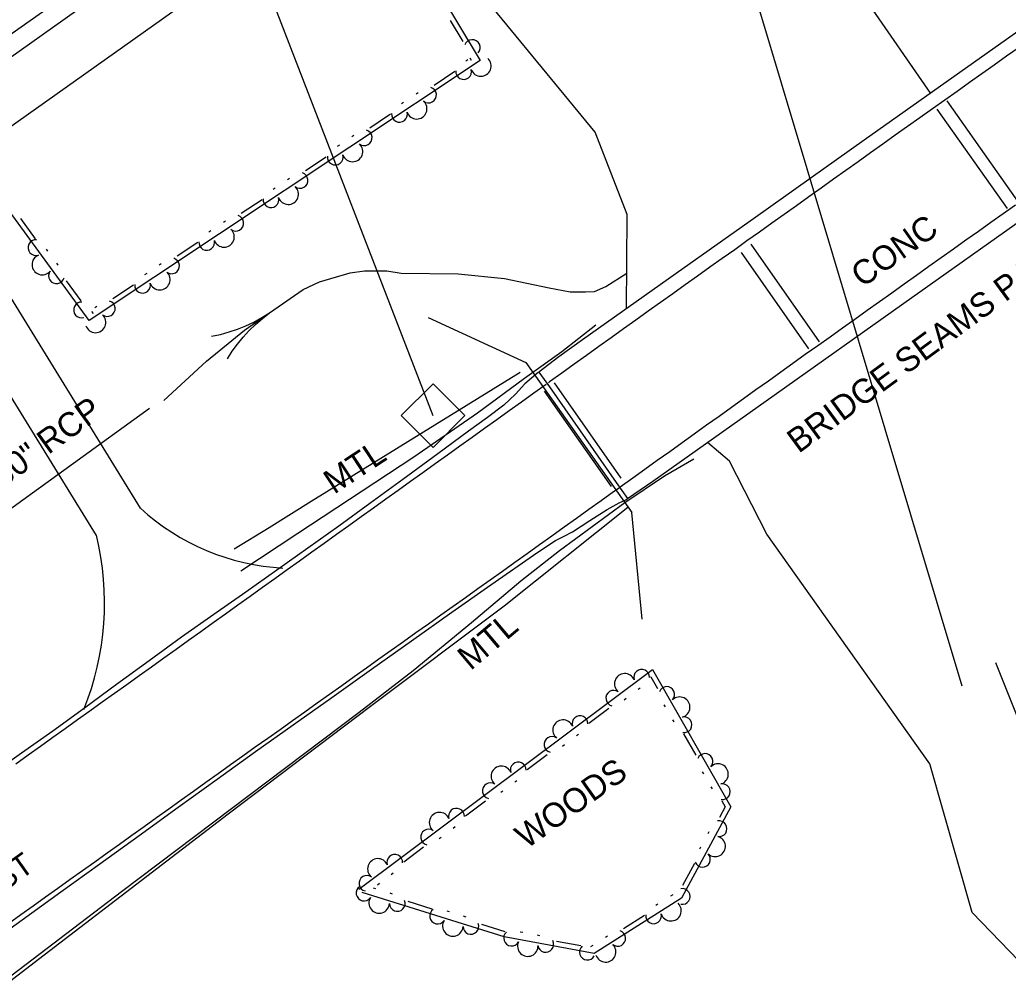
# Model space of a CAD drawing. Extents: x 1577032 to 1581865, y 611492 to 615011.
# Drawn here: x 1579630.9 to 1579793.8, y 613198.6 to 613356.4 of the extents above; entities that cross this region are included whole.
import ezdxf

# ---------------------------------------------------------------- set-up
doc = ezdxf.new("R2010")
doc.units = 0
for name, color, linetype in [('CTL Supplemental Horizontal and Vertical CELL', 7, 'Continuous'), ('Exist Guardrail', 7, 'Continuous'), ('Exist Guardrail Text', 7, 'Continuous'), ('Exist Horizontal Baseline Alignment Station Label', 7, 'Continuous'), ('Exist Hydro Jurisdictional Stream or Body of Water', 7, 'Continuous'), ('Exist Hydro Stream Flow Arrow CELL', 7, 'Continuous'), ('Exist Hydro Stream or Body of Water', 7, 'Continuous'), ('Exist Property Tie Line', 7, 'Continuous'), ('Exist Right of Way Line', 7, 'Continuous'), ('Exist Roads EOP', 7, 'Continuous'), ('Exist Roads EOP Text', 7, 'Continuous'), ('Exist Roads EOT', 7, 'Continuous'), ('Exist Structure Major Bridge Seam', 7, 'Continuous'), ('Exist Structure Major Bridge WW', 7, 'Continuous'), ('Exist Structure Major Deck Tunnel Box Culvert', 7, 'Continuous'), ('Exist Structure Major Deck Tunnel Box Culvert Text', 7, 'Continuous'), ('Exist Structure Minor Pipes RCP 30 Inch', 7, 'Continuous'), ('Exist Structure Minor Pipes RCP 30 Inch Text', 7, 'Continuous'), ('Exist Utilities Telephone UG FO SUE LOS B', 7, 'Continuous'), ('Exist Utilities Water UG Line SUE LOS B', 7, 'Continuous'), ('Exist Vegetation Woods Line Text', 7, 'Continuous'), ('Old_Level_11', 7, 'Continuous'), ('Old_Level_7', 7, 'Continuous'), ('Scratch_Level_3', 7, 'Continuous'), ('Scratch_Level_4', 7, 'Continuous')]:
    doc.layers.add(name, color=color, linetype=linetype)

msp = doc.modelspace()

# ---------------------------------------------------------------- linework, layer by layer
at = {"layer": 'CTL Supplemental Horizontal and Vertical CELL'}
msp.add_line((1579698.95, 613291.12), (1579698.95, 613291.12), dxfattribs=at)
msp.add_lwpolyline([(1579693.73, 613291.13), (1579698.97, 613296.38), (1579704.22, 613291.13), (1579698.98, 613285.88)], close=True, dxfattribs=at)
at = {"layer": 'Exist Guardrail'}
for points in [[(1579667.28, 613265.53), (1579676.67, 613271.75), (1579695.81, 613284.34), (1579706.32, 613291.56), (1579714.04, 613297.28), (1579720.19, 613301.68), (1579725.79, 613306.06)], [(1579741.96, 613283.96), (1579737.12, 613281.13), (1579730.57, 613276.73), (1579719.79, 613268.84), (1579713.42, 613263.83), (1579705.29, 613256.98), (1579695.7, 613249.06), (1579686.81, 613242.18), (1579647.6, 613212.65), (1579618.22, 613190.29), (1579587.73, 613167.25), (1579572.92, 613156.39), (1579515.84, 613115.84), (1579461.27, 613076.76), (1579417.23, 613045.78), (1579363.89, 613007.87), (1579309.01, 612968.33), (1579291.73, 612955.85)]]:
    msp.add_lwpolyline(points, dxfattribs=at)
at = {"layer": 'Exist Horizontal Baseline Alignment Station Label'}
msp.add_line((1579637.33, 613450.53), (1579698.95, 613291.12), dxfattribs=at)
at = {"layer": 'Exist Hydro Jurisdictional Stream or Body of Water'}
for points in [[(1579725.68, 613337.86), (1579702.45, 613366.13), (1579690.36, 613388.32), (1579685.84, 613407.56), (1579687.53, 613428.23), (1579681.01, 613453.54), (1579684.84, 613469.8), (1579686.57, 613483.26), (1579683.27, 613517.5), (1579681.81, 613542.23), (1579681.11, 613568.29), (1579677.24, 613598.35)], [(1579761.5, 613367.04), (1579770.44, 613359.38), (1579780.93, 613344.22)], [(1579730.85, 613308.77), (1579730.9, 613316.26), (1579730.95, 613324.27), (1579725.68, 613337.86)], [(1579831.32, 613164.67), (1579822.56, 613181.34), (1579806.35, 613190.1), (1579787.81, 613209.26), (1579780.85, 613233.72), (1579753.99, 613271.61), (1579747.82, 613283.64), (1579744.18, 613286.7)]]:
    msp.add_lwpolyline(points, dxfattribs=at)
at = {"layer": 'Exist Hydro Stream Flow Arrow CELL'}
msp.add_line((1579667.89, 613305.19), (1579667.89, 613305.19), dxfattribs=at)
for points in [[(1579662.47, 613304.23), (1579663.92, 613304.49), (1579665.35, 613304.93), (1579666.76, 613305.37), (1579668.1, 613305.92), (1579669.44, 613306.55), (1579670.75, 613307.27), (1579672, 613308.04)], [(1579665.08, 613300.46), (1579665.84, 613301.72), (1579666.75, 613302.91), (1579667.66, 613304.07), (1579668.64, 613305.14), (1579669.71, 613306.16), (1579670.84, 613307.14), (1579672, 613308.04)]]:
    msp.add_lwpolyline(points, dxfattribs=at)
at = {"layer": 'Exist Hydro Stream or Body of Water'}
msp.add_lwpolyline([(1579654.58, 613293.6), (1579661.66, 613300.1), (1579667.89, 613305.19), (1579677.59, 613311.91), (1579680.25, 613313.17), (1579685.29, 613314.64), (1579687.69, 613314.97), (1579691.37, 613314.97), (1579693.7, 613314.61), (1579703.1, 613314.47), (1579710.72, 613313.71), (1579718.12, 613312.17), (1579721.58, 613311.52), (1579724.08, 613311.5), (1579725.57, 613311.6), (1579727.45, 613312.38), (1579730.89, 613314.6)], dxfattribs=at)
at = {"layer": 'Exist Property Tie Line'}
for p, q in [((1579786.17, 613246.53), (1579735.91, 613414.45)), ((1579791.65, 613250.42), (1579814.68, 613192.73))]:
    msp.add_line(p, q, dxfattribs=at)
at = {"layer": 'Exist Right of Way Line'}
msp.add_line((1579178.76, 613018.8), (1580074.87, 613655.16), dxfattribs=at)
at = {"layer": 'Exist Roads EOP'}
for points in [[(1579716.3, 613298.21), (1579714.11, 613296.34), (1579712.54, 613294.68), (1579710.64, 613292.82), (1579707.97, 613290.83), (1579704.81, 613288.54), (1579699.78, 613284.85), (1579694, 613280.6), (1579688.56, 613276.63), (1579683.43, 613272.91), (1579678.34, 613269.27), (1579673.24, 613265.66), (1579668.1, 613262.05), (1579662.85, 613258.35), (1579657.51, 613254.59), (1579652.17, 613250.74), (1579646.82, 613246.8), (1579641.51, 613242.91), (1579636.3, 613239.15), (1579631.14, 613235.52), (1579625.91, 613231.84)], [(1579624.89, 613203.47), (1579631.25, 613208.06), (1579637.64, 613212.66), (1579644.08, 613217.29), (1579650.53, 613221.95), (1579656.98, 613226.61), (1579663.39, 613231.23), (1579669.7, 613235.75), (1579675.94, 613240.18), (1579682.3, 613244.69), (1579688.81, 613249.33), (1579695.42, 613254.02), (1579702.06, 613258.71), (1579708.5, 613263.24), (1579716.25, 613268.64), (1579719.16, 613270.54), (1579720.48, 613271.21), (1579721.94, 613271.97), (1579724.82, 613273.86), (1579727.66, 613275.63), (1579729.65, 613276.73), (1579730.73, 613277.27), (1579730.98, 613277.42)]]:
    msp.add_lwpolyline(points, dxfattribs=at)
at = {"layer": 'Exist Roads EOT'}
for points in [[(1579795.55, 613351.78), (1579793.5, 613350.33), (1579791.46, 613348.89), (1579789.42, 613347.44), (1579787.38, 613346), (1579785.34, 613344.55), (1579783.3, 613343.11), (1579781.26, 613341.66), (1579779.22, 613340.22), (1579777.18, 613338.77), (1579775.14, 613337.33), (1579773.11, 613335.88), (1579771.07, 613334.43), (1579769.04, 613332.97), (1579767, 613331.52), (1579764.96, 613330.07), (1579762.93, 613328.62), (1579760.89, 613327.17), (1579758.86, 613325.72), (1579756.82, 613324.27), (1579754.79, 613322.82), (1579752.75, 613321.37), (1579750.71, 613319.92), (1579748.68, 613318.47), (1579746.64, 613317.02), (1579744.61, 613315.56), (1579742.57, 613314.11), (1579740.53, 613312.66), (1579738.5, 613311.21), (1579736.46, 613309.76), (1579734.43, 613308.31), (1579732.39, 613306.86), (1579730.36, 613305.4), (1579728.33, 613303.95), (1579726.29, 613302.49), (1579724.26, 613301.03), (1579722.23, 613299.58), (1579720.2, 613298.12), (1579718.16, 613296.67), (1579717.99, 613296.54)], [(1579729.83, 613279.4), (1579731.87, 613280.86), (1579733.9, 613282.31), (1579735.93, 613283.77), (1579737.97, 613285.22), (1579740, 613286.68), (1579742.03, 613288.13), (1579744.06, 613289.59), (1579746.1, 613291.04), (1579748.13, 613292.5), (1579750.16, 613293.96), (1579752.19, 613295.41), (1579754.23, 613296.87), (1579756.26, 613298.32), (1579758.29, 613299.78), (1579760.32, 613301.23), (1579762.36, 613302.68), (1579764.4, 613304.13), (1579766.43, 613305.58), (1579768.47, 613307.03), (1579770.51, 613308.48), (1579772.54, 613309.93), (1579774.58, 613311.38), (1579776.62, 613312.83), (1579778.65, 613314.28), (1579780.69, 613315.73), (1579782.73, 613317.18), (1579784.76, 613318.63), (1579786.8, 613320.08), (1579788.84, 613321.53), (1579790.87, 613322.98), (1579792.91, 613324.43), (1579794.95, 613325.88)], [(1579717.6, 613296.27), (1579715.57, 613294.81), (1579713.54, 613293.35), (1579711.51, 613291.9), (1579709.48, 613290.44), (1579707.44, 613288.99), (1579705.41, 613287.53), (1579703.38, 613286.08), (1579701.35, 613284.62), (1579699.31, 613283.16), (1579697.28, 613281.71), (1579695.25, 613280.25), (1579693.22, 613278.8), (1579691.18, 613277.34), (1579689.15, 613275.89), (1579687.12, 613274.43), (1579685.09, 613272.98), (1579683.05, 613271.52), (1579681.02, 613270.07), (1579678.99, 613268.61), (1579676.95, 613267.16), (1579674.92, 613265.7), (1579672.89, 613264.25), (1579670.86, 613262.79), (1579668.82, 613261.34), (1579666.79, 613259.88), (1579664.76, 613258.43), (1579662.73, 613256.97), (1579660.69, 613255.52), (1579658.66, 613254.06), (1579656.63, 613252.6), (1579654.59, 613251.15), (1579652.56, 613249.69), (1579650.53, 613248.24), (1579648.5, 613246.78), (1579646.46, 613245.33), (1579644.43, 613243.88), (1579642.39, 613242.42), (1579640.36, 613240.97), (1579638.32, 613239.52), (1579636.29, 613238.07), (1579634.26, 613236.61), (1579632.22, 613235.16), (1579630.19, 613233.71)], [(1579629.01, 613207.44), (1579631.04, 613208.89), (1579633.08, 613210.35), (1579635.11, 613211.8), (1579637.14, 613213.26), (1579639.18, 613214.71), (1579641.21, 613216.17), (1579643.24, 613217.62), (1579645.28, 613219.07), (1579647.31, 613220.53), (1579649.34, 613221.98), (1579651.38, 613223.44), (1579653.41, 613224.89), (1579655.44, 613226.35), (1579657.48, 613227.8), (1579659.51, 613229.26), (1579661.54, 613230.71), (1579663.58, 613232.17), (1579665.61, 613233.62), (1579667.64, 613235.07), (1579669.68, 613236.52), (1579671.72, 613237.97), (1579673.76, 613239.42), (1579675.79, 613240.87), (1579677.83, 613242.32), (1579679.87, 613243.77), (1579681.9, 613245.22), (1579683.94, 613246.67), (1579685.98, 613248.12), (1579688.01, 613249.57), (1579690.05, 613251.02), (1579692.09, 613252.47), (1579694.12, 613253.92), (1579696.16, 613255.37), (1579698.2, 613256.82), (1579700.23, 613258.27), (1579702.27, 613259.71), (1579704.31, 613261.16), (1579706.34, 613262.61), (1579708.38, 613264.06), (1579710.42, 613265.51), (1579712.46, 613266.96), (1579714.49, 613268.41), (1579716.52, 613269.87), (1579718.56, 613271.32), (1579720.59, 613272.78), (1579722.62, 613274.24), (1579724.65, 613275.69), (1579726.69, 613277.15), (1579728.72, 613278.6), (1579729.63, 613279.25)]]:
    msp.add_lwpolyline(points, dxfattribs=at)
at = {"layer": 'Exist Structure Major Bridge Seam'}
for p, q in [((1579795.32, 613326.46), (1579783.71, 613343.01)), ((1579795.32, 613326.46), (1579783.71, 613343.01)), ((1579782.02, 613341.63), (1579793.59, 613325.27)), ((1579782.02, 613341.63), (1579793.59, 613325.27)), ((1579749.76, 613318.02), (1579760.85, 613302.15)), ((1579749.76, 613318.02), (1579760.85, 613302.15)), ((1579762.65, 613303.29), (1579751.41, 613319.36)), ((1579762.65, 613303.29), (1579751.41, 613319.36)), ((1579717.28, 613295.18), (1579728.35, 613279.44)), ((1579717.28, 613295.18), (1579728.35, 613279.44)), ((1579729.99, 613280.8), (1579718.99, 613296.5)), ((1579729.99, 613280.8), (1579718.99, 613296.5))]:
    msp.add_line(p, q, dxfattribs=at)
at = {"layer": 'Exist Structure Major Bridge WW'}
for points in [[(1579698.16, 613307.28), (1579714.28, 613299.88)], [(1579714.28, 613299.88), (1579731.73, 613275.14)], [(1579733.41, 613257.56), (1579731.73, 613275.14)]]:
    msp.add_lwpolyline(points, dxfattribs=at)
at = {"layer": 'Exist Structure Major Deck Tunnel Box Culvert'}
msp.add_lwpolyline([(1579827.3, 613348.19), (1579814.88, 613365.36), (1579813.5, 613367.27), (1579799.63, 613357.47), (1579792.53, 613352.42), (1579770.02, 613336.52), (1579752.16, 613323.84), (1579739.02, 613314.56), (1579723.58, 613303.6), (1579719.7, 613300.83), (1579716.41, 613298.3), (1579718.14, 613295.84), (1579729.17, 613280.12), (1579731.04, 613277.46), (1579735.17, 613280.34), (1579753.85, 613293.54), (1579777.85, 613310.57), (1579796.19, 613323.54), (1579810.87, 613333.95), (1579825.71, 613344.51), (1579828.51, 613346.49)], close=True, dxfattribs=at)
at = {"layer": 'Exist Structure Minor Pipes RCP 30 Inch'}
msp.add_line((1579625.4, 613272.92), (1579652.22, 613292.37), dxfattribs=at)
at = {"layer": 'Exist Utilities Telephone UG FO SUE LOS B'}
msp.add_lwpolyline([(1579251.42, 613079.81), (1579314.27, 613123.97), (1579356.61, 613152.5), (1579497.4, 613253.81), (1579521.61, 613271), (1579539.5, 613284.38), (1579578.9, 613312.67), (1579610.42, 613336.81), (1579656.92, 613369.78), (1579663.28, 613373.7), (1579685.42, 613390.38), (1579744.99, 613433.57), (1579762.43, 613445.5), (1579805.52, 613477.49)], dxfattribs=at)
at = {"layer": 'Exist Utilities Water UG Line SUE LOS B'}
msp.add_line((1579608.93, 613339.63), (1579657.38, 613373.69), dxfattribs=at)
at = {"layer": 'Old_Level_11'}
for points in [[(1579668.31, 613574.9), (1579674.96, 613547.45), (1579676.53, 613532.3), (1579675.8, 613513.47), (1579676.54, 613496.46), (1579676.51, 613478.85), (1579676.6, 613462.83), (1579677.63, 613443.92), (1579681.14, 613430.42), (1579681.23, 613408.68), (1579684.32, 613387.86), (1579693.46, 613371.76), (1579706.72, 613349.62), (1579642.32, 613306.79), (1579612.01, 613348.24), (1579582.34, 613397.36), (1579537.68, 613478.58)], [(1579701.78, 613356.26), (1579703.89, 613352.75)], [(1579704.71, 613349.75), (1579704.37, 613349.53)], [(1579705.01, 613350.07), (1579705.23, 613349.72)], [(1579702.54, 613347.82), (1579699.13, 613345.55)], [(1579696.51, 613344.3), (1579696.17, 613344.08)], [(1579694.12, 613342.71), (1579693.78, 613342.49)], [(1579691.96, 613340.78), (1579688.54, 613338.51)], [(1579685.93, 613337.26), (1579685.58, 613337.04)], [(1579683.54, 613335.67), (1579683.19, 613335.45)], [(1579681.37, 613333.74), (1579677.96, 613331.47)], [(1579675.34, 613330.22), (1579675, 613329.99)], [(1579672.95, 613328.63), (1579672.61, 613328.41)], [(1579670.79, 613326.7), (1579667.37, 613324.43)], [(1579633.47, 613320.28), (1579631.05, 613323.6)], [(1579664.75, 613323.18), (1579664.41, 613322.95)], [(1579662.36, 613321.59), (1579662.02, 613321.36)], [(1579660.2, 613319.66), (1579656.79, 613317.39)], [(1579635.49, 613318.21), (1579635.25, 613318.54)], [(1579637.19, 613315.89), (1579636.95, 613316.22)], [(1579654.17, 613316.14), (1579653.83, 613315.91)], [(1579640.97, 613310.02), (1579638.55, 613313.33)], [(1579651.78, 613314.55), (1579651.44, 613314.32)], [(1579649.61, 613312.62), (1579646.2, 613310.35)], [(1579643, 613307.95), (1579642.76, 613308.28)], [(1579643.58, 613309.1), (1579643.24, 613308.87)], [(1579686.75, 613213.07), (1579735.11, 613249.31), (1579748.07, 613226.67), (1579739.89, 613211.59), (1579725.5, 613202.51), (1579710.67, 613205.25), (1579687.28, 613212.55)], [(1579734.83, 613248.08), (1579734.85, 613248.1), (1579735.95, 613246.18)], [(1579732.78, 613246.03), (1579733.1, 613246.27)], [(1579730.48, 613244.31), (1579730.81, 613244.55)], [(1579737.02, 613243.48), (1579737.23, 613243.13)], [(1579724.65, 613240.45), (1579727.94, 613242.91)], [(1579738.45, 613240.99), (1579738.65, 613240.64)], [(1579722.6, 613238.4), (1579722.93, 613238.65)], [(1579740.23, 613238.71), (1579742.27, 613235.15)], [(1579720.31, 613236.68), (1579720.63, 613236.93)], [(1579714.48, 613232.83), (1579717.76, 613235.29)], [(1579743.34, 613232.45), (1579743.55, 613232.1)], [(1579712.43, 613230.78), (1579712.76, 613231.02)], [(1579744.77, 613229.96), (1579744.97, 613229.61)], [(1579710.13, 613229.05), (1579710.46, 613229.3)], [(1579704.31, 613225.2), (1579707.59, 613227.66)], [(1579746.55, 613227.67), (1579747.13, 613226.66), (1579746.17, 613224.89)], [(1579702.26, 613223.15), (1579702.59, 613223.4)], [(1579744.44, 613222.56), (1579744.24, 613222.2)], [(1579699.96, 613221.43), (1579700.29, 613221.68)], [(1579694.14, 613217.58), (1579697.42, 613220.04)], [(1579743.07, 613220.03), (1579742.87, 613219.67)], [(1579742.06, 613217.32), (1579740.1, 613213.71)], [(1579692.09, 613215.53), (1579692.41, 613215.77)], [(1579689.79, 613213.8), (1579690.12, 613214.05)], [(1579689.53, 613213.14), (1579689.14, 613213.26)], [(1579692.27, 613212.28), (1579691.88, 613212.41)], [(1579738.47, 613212.15), (1579738.12, 613211.93)], [(1579698.8, 613209.82), (1579694.89, 613211.04)], [(1579736.04, 613210.62), (1579735.69, 613210.4)], [(1579701.67, 613209.35), (1579701.27, 613209.47)], [(1579704.41, 613208.5), (1579704.01, 613208.62)], [(1579710.87, 613206.05), (1579707.02, 613207.25)], [(1579733.83, 613208.74), (1579730.36, 613206.55)], [(1579713.74, 613205.94), (1579713.34, 613206.01)], [(1579716.56, 613205.41), (1579716.16, 613205.49)], [(1579723.35, 613203.74), (1579719.31, 613204.49)], [(1579727.72, 613205.36), (1579727.37, 613205.14)], [(1579725.29, 613203.83), (1579724.94, 613203.61)]]:
    msp.add_lwpolyline(points, dxfattribs=at)
for centre, radius, start, end in [((1579705.44, 613351.76), 1.3, 319.3503, 160.1469), ((1579706.87, 613348.73), 1.69, 199.5911, 47.6636), ((1579704.02, 613347.82), 1.3, 174.3959, 15.1924), ((1579698.22, 613343.96), 1.3, 232.0623, 72.8589), ((1579696.28, 613341.69), 1.69, 199.5911, 47.6636), ((1579693.44, 613340.78), 1.3, 174.3959, 15.1924), ((1579687.63, 613336.92), 1.3, 232.0623, 72.8589), ((1579685.7, 613334.65), 1.69, 199.5911, 47.6636), ((1579682.85, 613333.74), 1.3, 174.3959, 15.1924), ((1579677.05, 613329.88), 1.3, 232.0623, 72.8589), ((1579675.11, 613327.61), 1.69, 199.5911, 47.6636), ((1579672.27, 613326.7), 1.3, 174.3959, 15.1924), ((1579666.46, 613322.84), 1.3, 232.0623, 72.8589), ((1579664.52, 613320.57), 1.69, 199.5911, 47.6636), ((1579633.53, 613318.81), 1.3, 86.9413, 287.7379), ((1579661.68, 613319.66), 1.3, 174.3959, 15.1924), ((1579634.57, 613316.01), 1.69, 112.1366, 320.2091), ((1579655.87, 613315.8), 1.3, 232.0623, 72.8589), ((1579636.92, 613314.17), 1.3, 144.6078, 345.4043), ((1579653.94, 613313.53), 1.69, 199.5911, 47.6636), ((1579651.09, 613312.62), 1.3, 174.3959, 15.1924), ((1579641.04, 613308.54), 1.3, 86.9413, 287.7379), ((1579645.29, 613308.76), 1.3, 232.0623, 72.8589), ((1579643.35, 613306.48), 1.69, 199.5911, 47.6636), ((1579730.56, 613246.93), 1.69, 22.8175, 230.89), ((1579733.35, 613248), 1.3, 357.6222, 198.4188), ((1579737.48, 613245.16), 1.3, 318.2305, 159.0271), ((1579728.76, 613244.55), 1.3, 55.2887, 256.0852), ((1579739.62, 613243.08), 1.69, 285.7594, 133.8318), ((1579723.18, 613240.37), 1.3, 357.6222, 198.4188), ((1579740.33, 613240.18), 1.3, 260.5641, 101.3607), ((1579720.39, 613239.3), 1.69, 22.8175, 230.89), ((1579718.58, 613236.93), 1.3, 55.2887, 256.0852), ((1579743.8, 613234.13), 1.3, 318.2305, 159.0271), ((1579710.22, 613231.68), 1.69, 22.8175, 230.89), ((1579713.01, 613232.74), 1.3, 357.6222, 198.4188), ((1579745.94, 613232.05), 1.69, 285.7594, 133.8318), ((1579708.41, 613229.3), 1.3, 55.2887, 256.0852), ((1579746.65, 613229.15), 1.3, 260.5641, 101.3607), ((1579700.04, 613224.05), 1.69, 22.8175, 230.89), ((1579702.83, 613225.12), 1.3, 357.6222, 198.4188), ((1579746.11, 613223.05), 1.3, 259.953, 100.7496), ((1579698.24, 613221.68), 1.3, 55.2887, 256.0852), ((1579745.46, 613220.14), 1.69, 227.4818, 75.5543), ((1579692.66, 613217.49), 1.3, 357.6222, 198.4188), ((1579743.37, 613218.01), 1.3, 202.2865, 43.0831), ((1579689.87, 613216.43), 1.69, 22.8175, 230.89), ((1579688.07, 613214.05), 1.3, 55.2887, 256.0852), ((1579687.6, 613212.45), 1.3, 123.4397, 324.2363), ((1579740.04, 613211.88), 1.3, 259.953, 100.7496), ((1579690.09, 613210.82), 1.69, 148.635, 356.7075), ((1579693.08, 613210.74), 1.3, 181.1062, 21.9028), ((1579738.18, 613209.54), 1.69, 198.2157, 46.2882), ((1579699.73, 613208.67), 1.3, 123.4397, 324.2363), ((1579735.31, 613208.7), 1.3, 173.0204, 13.817), ((1579702.23, 613207.03), 1.69, 148.635, 356.7075), ((1579705.21, 613206.96), 1.3, 181.1062, 21.9028), ((1579711.91, 613205.03), 1.3, 130.2758, 331.0723), ((1579729.41, 613204.98), 1.3, 230.6869, 71.4834), ((1579714.58, 613203.7), 1.69, 155.471, 3.5435), ((1579717.55, 613203.98), 1.3, 187.9422, 28.7388), ((1579727.42, 613202.75), 1.69, 198.2157, 46.2882), ((1579724.41, 613202.71), 1.3, 130.2758, 331.0723)]:
    msp.add_arc(centre, radius, start, end, dxfattribs=at)
at = {"layer": 'Old_Level_7'}
for points in [[(1579666.17, 613269.17), (1579671.96, 613272.67), (1579678.88, 613277), (1579713.3, 613298.31)], [(1579731.09, 613276.01), (1579710.7, 613259.75), (1579688.64, 613243.19), (1579665.21, 613225.45), (1579633.23, 613200.96)], [(1579633.23, 613200.96), (1579607.11, 613180.86), (1579580.36, 613161.21), (1579524.24, 613121.13), (1579478.41, 613088.53), (1579436.79, 613059.35), (1579401.7, 613034.42), (1579375.63, 613015.91), (1579345.59, 612994.44), (1579319.84, 612975.64), (1579293.12, 612956.3)]]:
    msp.add_lwpolyline(points, dxfattribs=at)
at = {"layer": 'Scratch_Level_4'}
for points in [[(1579650.75, 613275.86), (1579581.91, 613387.66), (1579536.35, 613471.68)], [(1579643.48, 613271.39), (1579574.52, 613383.38), (1579528.85, 613467.61)]]:
    msp.add_lwpolyline(points, dxfattribs=at)
for centre, radius, start, end in [((1579676.34, 613303.98), 38.03, 227.6867, 266.8199), ((1579598.33, 613260.24), 46.51, 337.8585, 13.8795)]:
    msp.add_arc(centre, radius, start, end, dxfattribs=at)

# ---------------------------------------------------------------- texts
at = {"layer": 'Exist Guardrail Text'}
for rotation, p in [(33.3283, (1579682.66, 613278.08)), (40.1006, (1579705.15, 613249.02))]:
    msp.add_text('MTL', height=4, rotation=rotation, dxfattribs=at).set_placement(p)
at = {"layer": 'Exist Roads EOP Text'}
msp.add_text("22' BST", height=3.691, rotation=35.38, dxfattribs=at).set_placement((1579619.28, 613206.25))
at = {"layer": 'Exist Structure Major Deck Tunnel Box Culvert Text'}
msp.add_text('CONC', height=4, rotation=35.38, dxfattribs=at).set_placement((1579769.7, 613312.11))
at = {"layer": 'Exist Structure Minor Pipes RCP 30 Inch Text'}
msp.add_text('30" RCP', height=4, rotation=35.9442, dxfattribs=at).set_placement((1579628.01, 613279.14))
at = {"layer": 'Exist Vegetation Woods Line Text'}
msp.add_text('WOODS', height=4, rotation=35.38, dxfattribs=at).set_placement((1579714.36, 613219.61))
at = {"layer": 'Scratch_Level_3'}
msp.add_text('BRIDGE SEAMS PAVED OVER', height=4, rotation=36.2551, dxfattribs=at).set_placement((1579759.22, 613284.8))

doc.saveas('drawing.dxf')
